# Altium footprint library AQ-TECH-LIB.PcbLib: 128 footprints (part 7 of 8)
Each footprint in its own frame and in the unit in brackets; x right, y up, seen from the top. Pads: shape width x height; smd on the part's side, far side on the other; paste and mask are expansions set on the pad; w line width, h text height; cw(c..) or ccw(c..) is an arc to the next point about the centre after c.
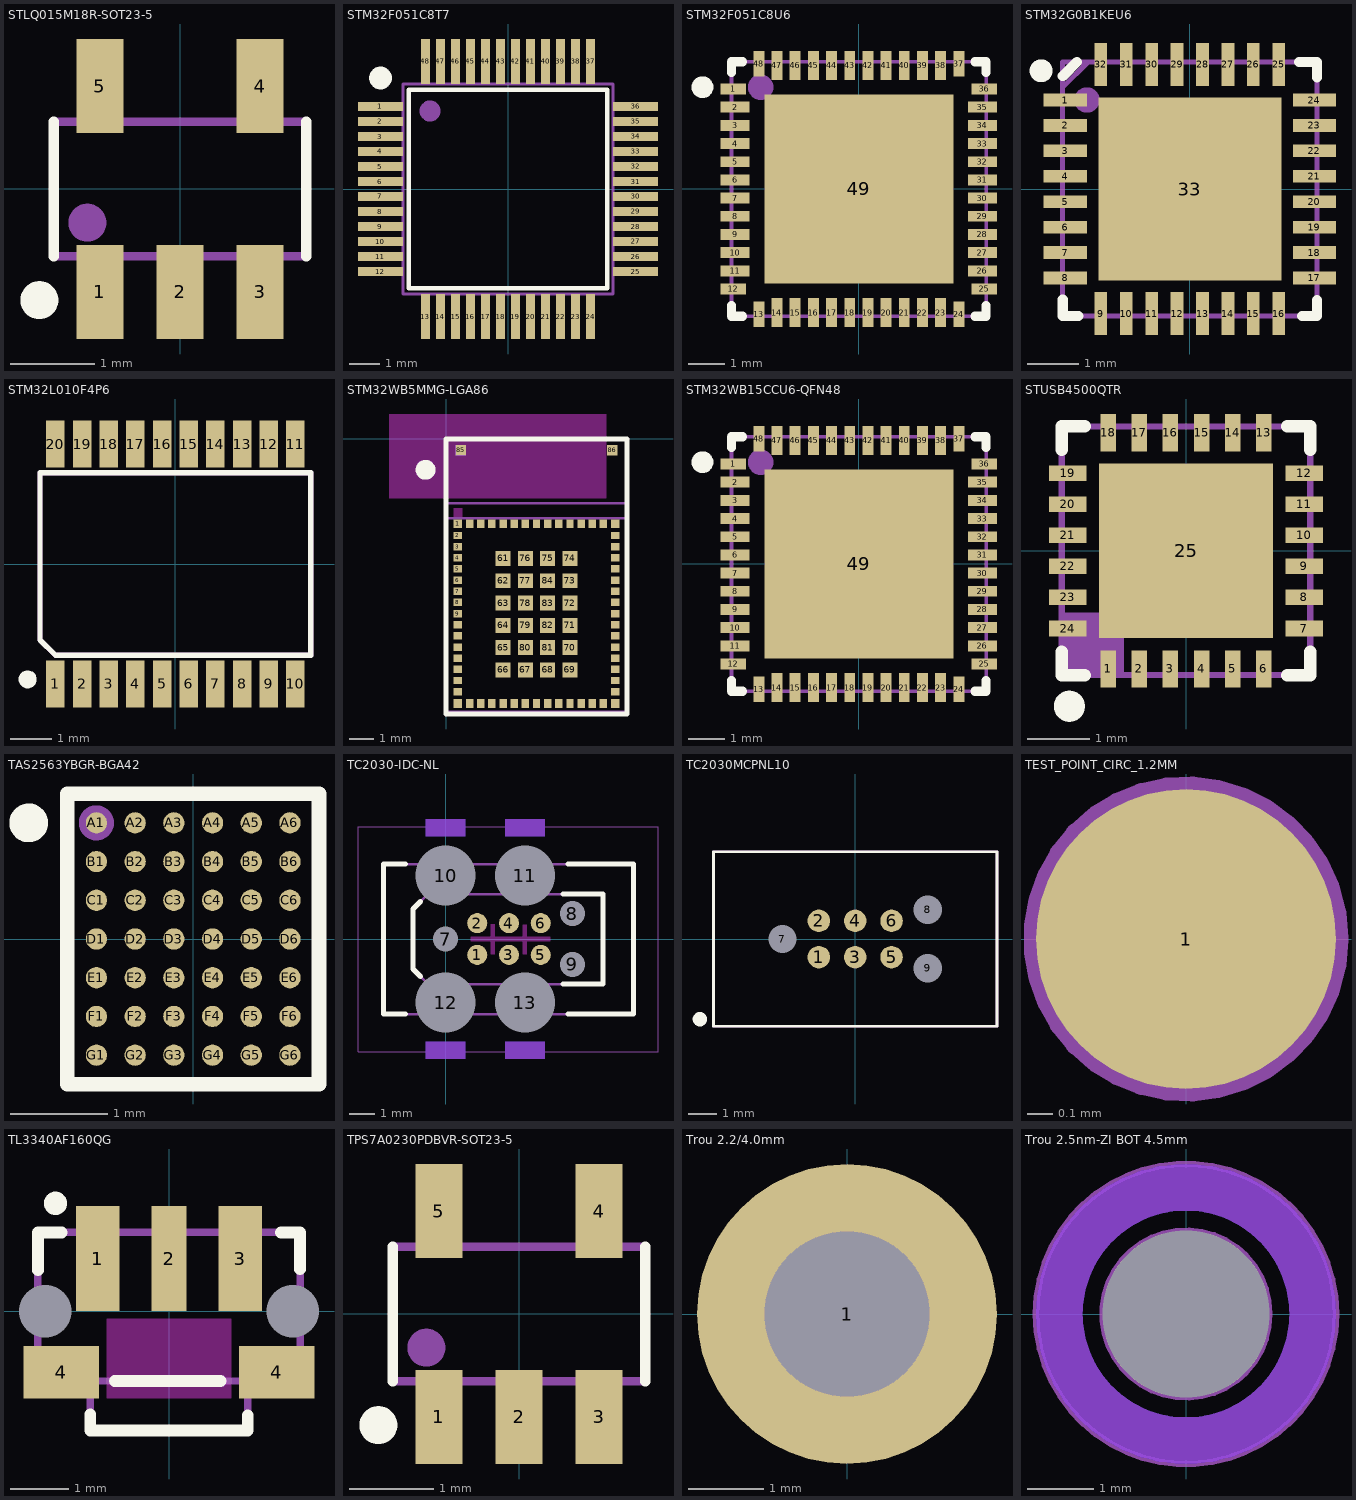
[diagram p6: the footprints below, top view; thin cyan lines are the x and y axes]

## STLQ015M18R-SOT23-5 [mil]
height 57.09
pads (5):
  rect 22x44 smd: 1(-37.4,-48.11) 2(0,-48.11) 3(37.4,-48.11) 4(37.4,48.11) 5(-37.4,48.11)
Top Overlay:
  lines w4.92: -59.06,-31.5 -59.06,31.5 ; 59.06,-31.5 59.06,31.5
  lines w9.84: -65.75,-55.91 ccw(c-65.75,-51.97) -65.75,-48.03 ccw(c-65.75,-51.97) -65.75,-55.91
Mechanical 3:
  lines w3.94: -59.06,-31.5 -59.06,31.5 59.06,31.5 59.06,-31.5 -59.06,-31.5
  lines w9.84: -43.31,-19.68 cw(c-43.31,-15.75) -43.31,-11.81 cw(c-43.31,-15.75) -43.31,-19.68
  text ".Designator" at -54.08,-9.65 h33.07
3D body "sot23-5.stp": height 43.31, standoff 0, extent -59.05,-49.2 59.06,49.22

## STM32F051C8T7 [mm]
height 1.6
pads (48):
  rect 1.5x0.3 smd paste+0 mask+0.05: 1(-4.25,2.75) 2(-4.25,2.25) 3(-4.25,1.75) 4(-4.25,1.25) 5(-4.25,0.75) 6(-4.25,0.25) 7(-4.25,-0.25) 8(-4.25,-0.75) 9(-4.25,-1.25) 10(-4.25,-1.75) 11(-4.25,-2.25) 12(-4.25,-2.75) 25(4.25,-2.75) 26(4.25,-2.25) 27(4.25,-1.75) 28(4.25,-1.25) 29(4.25,-0.75) 30(4.25,-0.25) 31(4.25,0.25) 32(4.25,0.75) 33(4.25,1.25) 34(4.25,1.75) 35(4.25,2.25) 36(4.25,2.75)
  rect 0.3x1.5 smd paste+0 mask+0.05: 13(-2.75,-4.25) 14(-2.25,-4.25) 15(-1.75,-4.25) 16(-1.25,-4.25) 17(-0.75,-4.25) 18(-0.25,-4.25) 19(0.25,-4.25) 20(0.75,-4.25) 21(1.25,-4.25) 22(1.75,-4.25) 23(2.25,-4.25) 24(2.75,-4.25) 37(2.75,4.25) 38(2.25,4.25) 39(1.75,4.25) 40(1.25,4.25) 41(0.75,4.25) 42(0.25,4.25) 43(-0.25,4.25) 44(-0.75,4.25) 45(-1.25,4.25) 46(-1.75,4.25) 47(-2.25,4.25) 48(-2.75,4.25)
Top Overlay:
  circle w0.4: c-4.25,3.7 r0.18
  lines w0.15: -3.3,-3.3 3.3,-3.3 3.3,3.3 -3.3,3.3 -3.3,-3.3
Mechanical 3:
  circle w0.4: c-2.6,2.6 r0.15
  lines w0.1: -3.5,-3.5 3.5,-3.5 3.5,3.5 -3.5,3.5 -3.5,-3.5
  text ".Designator" at -0.125,0.9 h0.84
3D body: height 1.6, standoff 0, extent -3.5,-3.5 3.5,3.5

## STM32F051C8U6 [mm] "UFQFPN48 7X7mm"
height 0.6
pads (49):
  rect 0.7x0.3 smd mask+0.05: 1(-3.45,2.75) 12(-3.45,-2.75) 25(3.45,-2.75) 36(3.45,2.75)
  rect 0.8x0.3 smd mask+0.05: 2(-3.4,2.25) 3(-3.4,1.75) 4(-3.4,1.25) 5(-3.4,0.75) 6(-3.4,0.25) 7(-3.4,-0.25) 8(-3.4,-0.75) 9(-3.4,-1.25) 10(-3.4,-1.75) 11(-3.4,-2.25) 26(3.4,-2.25) 27(3.4,-1.75) 28(3.4,-1.25) 29(3.4,-0.75) 30(3.4,-0.25) 31(3.4,0.25) 32(3.4,0.75) 33(3.4,1.25) 34(3.4,1.75) 35(3.4,2.25)
  rect 0.3x0.7 smd mask+0.05: 13(-2.75,-3.45) 24(2.75,-3.45) 37(2.75,3.45) 48(-2.75,3.45)
  rect 0.3x0.8 smd mask+0.05: 14(-2.25,-3.4) 15(-1.75,-3.4) 16(-1.25,-3.4) 17(-0.75,-3.4) 18(-0.25,-3.4) 19(0.25,-3.4) 20(0.75,-3.4) 21(1.25,-3.4) 22(1.75,-3.4) 23(2.25,-3.4) 38(2.25,3.4) 39(1.75,3.4) 40(1.25,3.4) 41(0.75,3.4) 42(0.25,3.4) 43(-0.25,3.4) 44(-0.75,3.4) 45(-1.25,3.4) 46(-1.75,3.4) 47(-2.25,3.4)
  rect 5.2x5.2 smd: 49(0,0)
Top Overlay:
  circle w0.3: c-4.3,2.8 r0.15
  lines w0.25: -3.5,-3.2 -3.5,-3.5 -3.2,-3.5 ; -3.5,3.2 -3.5,3.5 -3.2,3.5 ; 3.2,-3.5 3.5,-3.5 3.5,-3.2 ; 3.2,3.5 3.5,3.5 3.5,3.2
Mechanical 3:
  circle w0.4: c-2.7,2.8 r0.15
  lines w0.1: -3.5,-3.5 -3.5,3.5 3.5,3.5 3.5,-3.5 -3.5,-3.5
  text ".Designator" at -1.2,-0.1 h0.84
3D body: height 0.6, standoff 0, extent -3.5,-3.5 3.5,3.5
3D body: height 0.61, standoff 0, extent -2.898,2.201 -2.101,2.999

## STM32G0B1KEU6 [mm] "QFPN32-5X5mm"
height 0.6
pads (33):
  rect 0.85x0.25 smd mask+0.05: 1(-2.45,1.75) 2(-2.45,1.25) 3(-2.45,0.75) 4(-2.45,0.25) 5(-2.45,-0.25) 6(-2.45,-0.75) 7(-2.45,-1.25) 8(-2.45,-1.75) 17(2.45,-1.75) 18(2.45,-1.25) 19(2.45,-0.75) 20(2.45,-0.25) 21(2.45,0.25) 22(2.45,0.75) 23(2.45,1.25) 24(2.45,1.75)
  rect 0.25x0.85 smd mask+0.05: 9(-1.75,-2.45) 10(-1.25,-2.45) 11(-0.75,-2.45) 12(-0.25,-2.45) 13(0.25,-2.45) 14(0.75,-2.45) 15(1.25,-2.45) 16(1.75,-2.45) 25(1.75,2.45) 26(1.25,2.45) 27(0.75,2.45) 28(0.25,2.45) 29(-0.25,2.45) 30(-0.75,2.45) 31(-1.25,2.45) 32(-1.75,2.45)
  rect 3.6x3.6 smd mask+0.05: 33(0,0)
Top Overlay:
  circle w0.25: c-2.925,2.325 r0.1
  lines w0.2: -2.5,-2.17 -2.5,-2.5 -2.192,-2.5 ; -2.5,2.22 -2.218,2.5 ; 2.151,2.5 2.5,2.5 2.5,2.194 ; 2.208,-2.5 2.5,-2.5 2.5,-2.187
Mechanical 3:
  circle w0.3: c-2.025,1.75 r0.1
  lines w0.1: -2.5,2 -2,2.5 ; -2.5,-2.5 2.5,-2.5 2.5,2.5 -2.5,2.5 -2.5,-2.5
  text ".Designator" at -1.2,-0.1 h0.84
3D body "STM32G0B1KEU6.stp": height 0.6, standoff 0, extent -2.55,-2.55 2.55,2.55

## STM32L010F4P6 [mm] "refusion"
height 1.1
pads (20):
  rect 0.45x1.15 smd paste+0 mask+0.05: 1(-2.925,-2.925) 2(-2.275,-2.925) 3(-1.625,-2.925) 4(-0.975,-2.925) 5(-0.325,-2.925) 6(0.325,-2.925) 7(0.975,-2.925) 8(1.625,-2.925) 9(2.275,-2.925) 10(2.925,-2.925) 11(2.925,2.925) 12(2.275,2.925) 13(1.625,2.925) 14(0.975,2.925) 15(0.325,2.925) 16(-0.325,2.925) 17(-0.975,2.925) 18(-1.625,2.925) 19(-2.275,2.925) 20(-2.925,2.925)
Top Overlay:
  region: -3.6,-3.025 -3.642,-3.025 -3.72,-2.993 -3.78,-2.933 -3.812,-2.855 -3.812,-2.77 -3.78,-2.692 -3.72,-2.632 -3.642,-2.6 -3.6,-2.6 -3.558,-2.6 -3.48,-2.632 -3.42,-2.692 -3.387,-2.77 -3.388,-2.855 -3.42,-2.933 -3.48,-2.993 -3.558,-3.025
  lines w0.125: -3.3,-1.85 -3.3,2.225 3.3,2.225 3.3,-2.225 -2.925,-2.225 -3.3,-1.85
Mechanical 3:
  lines w0.125: -3.3,-1.85 -3.3,2.225 3.3,2.225 3.3,-2.225 -2.925,-2.225 -3.3,-1.85
  text "'.Designator'" at 0,0 h1
3D body "TSSOP20(refusion).stp": height 1.2, standoff 0, extent -3.3,-3.275 3.3,3.275

## STM32WB5MMG-LGA86 [mm] "7.3X11X1.4mm"
height 1.4
pads (86):
  rect 0.35x0.35 smd paste+0 mask+0.1: 1(0.475,-3.425) 17(0.475,-10.675) 31(6.825,-10.675) 47(6.825,-3.425)
  rect 0.35x0.3 smd paste+0 mask+0.1: 2(0.475,-3.9) 3(0.475,-4.35) 4(0.475,-4.8) 5(0.475,-5.25) 6(0.475,-5.7) 7(0.475,-6.15) 8(0.475,-6.6) 9(0.475,-7.05) 10(0.475,-7.5) 11(0.475,-7.95) 12(0.475,-8.4) 13(0.475,-8.85) 14(0.475,-9.3) 15(0.475,-9.75) 16(0.475,-10.2) 32(6.825,-10.2) 33(6.825,-9.75) 34(6.825,-9.3) 35(6.825,-8.85) 36(6.825,-8.4) 37(6.825,-7.95) 38(6.825,-7.5) 39(6.825,-7.05) 40(6.825,-6.6) 41(6.825,-6.15) 42(6.825,-5.7) 43(6.825,-5.25) 44(6.825,-4.8) 45(6.825,-4.35) 46(6.825,-3.9)
  rect 0.3x0.35 smd paste+0 mask+0.1: 18(0.95,-10.675) 19(1.4,-10.675) 20(1.85,-10.675) 21(2.3,-10.675) 22(2.75,-10.675) 23(3.2,-10.675) 24(3.65,-10.675) 25(4.1,-10.675) 26(4.55,-10.675) 27(5,-10.675) 28(5.45,-10.675) 29(5.9,-10.675) 30(6.35,-10.675) 48(6.35,-3.425) 49(5.9,-3.425) 50(5.45,-3.425) 51(5,-3.425) 52(4.55,-3.425) 53(4.1,-3.425) 54(3.65,-3.425) 55(3.2,-3.425) 56(2.75,-3.425) 57(2.3,-3.425) 58(1.85,-3.425) 59(1.4,-3.425) 60(0.95,-3.425)
  rect 0.6x0.6 smd paste+0 mask+0.1: 61(2.3,-4.825) 62(2.3,-5.725) 63(2.3,-6.625) 64(2.3,-7.525) 65(2.3,-8.425) 66(2.3,-9.325) 67(3.2,-9.325) 68(4.1,-9.325) 69(5,-9.325) 70(5,-8.425) 71(5,-7.525) 72(5,-6.625) 73(5,-5.725) 74(5,-4.825) 75(4.1,-4.825) 76(3.2,-4.825) 77(3.2,-5.725) 78(3.2,-6.625) 79(3.2,-7.525) 80(3.2,-8.425) 81(4.1,-8.425) 82(4.1,-7.525) 83(4.1,-6.625) 84(4.1,-5.725)
  rect 0.43x0.43 smd paste+0 mask+0.1: 85(0.6,-0.465) 86(6.7,-0.465)
Top Layer keep-out:
  rectangle: 0.295,-3.145 0.655,-2.8
Top Overlay:
  circle w0.5: c-0.825,-1.25 r0.15
  lines w0.2: 0,-11.1 7.3,-11.1 7.3,0 0,0 0,-11.1
Keep-Out Layer:
  rectangle: -2.3,-2.4 6.475,1
Mechanical 3:
  lines w0.1: 0,-3.2 7.3,-3.2 ; 0,-2.6 7.3,-2.6 ; 0,-11 0,0 7.3,0 7.3,-11 0,-11
  text ".Designator" at 3.6,-6.875 h0.84
3D body: height 1.41, standoff 0, extent 0.351,-1.35 0.849,-0.851
3D body: height 1.4, standoff 0, extent 0,-11 7.3,0

## STM32WB15CCU6-QFN48 [mm] "UFQFPN48 7X7mm"
height 0.6
pads (49):
  rect 0.7x0.3 smd mask+0.05: 1(-3.45,2.75) 12(-3.45,-2.75) 25(3.45,-2.75) 36(3.45,2.75)
  rect 0.8x0.3 smd mask+0.05: 2(-3.4,2.25) 3(-3.4,1.75) 4(-3.4,1.25) 5(-3.4,0.75) 6(-3.4,0.25) 7(-3.4,-0.25) 8(-3.4,-0.75) 9(-3.4,-1.25) 10(-3.4,-1.75) 11(-3.4,-2.25) 26(3.4,-2.25) 27(3.4,-1.75) 28(3.4,-1.25) 29(3.4,-0.75) 30(3.4,-0.25) 31(3.4,0.25) 32(3.4,0.75) 33(3.4,1.25) 34(3.4,1.75) 35(3.4,2.25)
  rect 0.3x0.7 smd mask+0.05: 13(-2.75,-3.45) 24(2.75,-3.45) 37(2.75,3.45) 48(-2.75,3.45)
  rect 0.3x0.8 smd mask+0.05: 14(-2.25,-3.4) 15(-1.75,-3.4) 16(-1.25,-3.4) 17(-0.75,-3.4) 18(-0.25,-3.4) 19(0.25,-3.4) 20(0.75,-3.4) 21(1.25,-3.4) 22(1.75,-3.4) 23(2.25,-3.4) 38(2.25,3.4) 39(1.75,3.4) 40(1.25,3.4) 41(0.75,3.4) 42(0.25,3.4) 43(-0.25,3.4) 44(-0.75,3.4) 45(-1.25,3.4) 46(-1.75,3.4) 47(-2.25,3.4)
  rect 5.2x5.2 smd: 49(0,0)
Top Overlay:
  circle w0.3: c-4.3,2.8 r0.15
  lines w0.25: -3.5,-3.2 -3.5,-3.5 -3.2,-3.5 ; -3.5,3.2 -3.5,3.5 -3.2,3.5 ; 3.2,-3.5 3.5,-3.5 3.5,-3.2 ; 3.2,3.5 3.5,3.5 3.5,3.2
Mechanical 3:
  circle w0.4: c-2.7,2.8 r0.15
  lines w0.1: -3.5,-3.5 3.5,-3.5 3.5,3.5 -3.5,3.5 -3.5,-3.5
  text ".Designator" at -1.2,-0.1 h0.84
3D body: height 0.61, standoff 0, extent -2.898,2.201 -2.101,2.999
3D body: height 0.6, standoff 0, extent -3.5,-3.5 3.5,3.5

## STUSB4500QTR [mm] "QFN24 4X4mm"
height 1
pads (25):
  rect 0.25x0.6 smd paste+0 mask+0.05: 1(-1.25,-1.9) 2(-0.75,-1.9) 3(-0.25,-1.9) 4(0.25,-1.9) 5(0.75,-1.9) 6(1.25,-1.9) 13(1.25,1.9) 14(0.75,1.9) 15(0.25,1.9) 16(-0.25,1.9) 17(-0.75,1.9) 18(-1.25,1.9)
  rect 0.6x0.25 smd paste+0 mask+0.05: 7(1.9,-1.25) 8(1.9,-0.75) 9(1.9,-0.25) 10(1.9,0.25) 11(1.9,0.75) 12(1.9,1.25) 19(-1.9,1.25) 20(-1.9,0.75) 21(-1.9,0.25) 22(-1.9,-0.25) 23(-1.9,-0.75) 24(-1.9,-1.25)
  rect 2.8x2.8 smd paste+0 mask+0.05: 25(0,0)
Top Overlay:
  lines w0.2: -2,-1.625 -2,-2 -1.625,-2 ; -2,1.625 -2,2 -1.625,2 ; 1.625,-2 2,-2 2,-1.625 ; 1.625,2 2,2 2,1.625
  lines w0.25: -1.875,-2.625 ccw(c-1.875,-2.5) -1.875,-2.375 ccw(c-1.875,-2.5) -1.875,-2.625
Mechanical 3:
  region: -2,-2 -1,-2 -1,-1 -2,-1
  lines w0.1: -2,-2 2,-2 2,2 -2,2 -2,-2
  text ".Designator" at 0,0 h0.84
3D body: height 1.01, standoff 0, extent -2,-2 -1,-1
3D body: height 1, standoff 0, extent -2,-2 2,2

## TAS2563YBGR-BGA42 [mm] "pas 0.4mm"
height 0.5
pads (42):
  round 0.22 smd mask+0.04: A1(-1,1.2) A2(-0.6,1.2) A3(-0.2,1.2) A4(0.2,1.2) A5(0.6,1.2) A6(1,1.2) B1(-1,0.8) B2(-0.6,0.8) B3(-0.2,0.8) B4(0.2,0.8) B5(0.6,0.8) B6(1,0.8) C1(-1,0.4) C2(-0.6,0.4) C3(-0.2,0.4) C4(0.2,0.4) C5(0.6,0.4) C6(1,0.4) D1(-1,0) D2(-0.6,0) D3(-0.2,0) D4(0.2,0) D5(0.6,0) D6(1,0) E1(-1,-0.4) E2(-0.6,-0.4) E3(-0.2,-0.4) E4(0.2,-0.4) E5(0.6,-0.4) E6(1,-0.4) F1(-1,-0.8) F2(-0.6,-0.8) F3(-0.2,-0.8) F4(0.2,-0.8) F5(0.6,-0.8) F6(1,-0.8) G1(-1,-1.2) G2(-0.6,-1.2) G3(-0.2,-1.2) G4(0.2,-1.2) G5(0.6,-1.2) G6(1,-1.2)
Top Overlay:
  circle w0.2: c-1.7,1.2 r0.1
  lines w0.15: -1.3,-1.5 -1.3,1.5 1.3,1.5 1.3,-1.5 -1.3,-1.5
Mechanical 3:
  circle w0.2: c-1,1.2 r0.081
  lines w0.1: -1.3,-1.5 -1.3,1.5 1.3,1.5 1.3,-1.5 -1.3,-1.5
  text "1" at -1.1,1.7 h0.5
  text "G" at -1.8,-1.4 h0.5
  text "6" at 0.9,1.7 h0.5
  text "A" at -1.8,1.1 h0.5
  text ".Designator" at -0.6,-0.4 h0.84
3D body: height 0.5, standoff 0, extent -1.3,-1.5 1.3,1.5
3D body: height 0.51, standoff 0, extent -1.124,1.075 -0.875,1.325

## TC2030-IDC-NL [mm]
height 27
pads (13):
  round 0.8 smd paste-0.8 mask+0.1: 1(1.27,-0.635) 2(1.27,0.635) 3(2.54,-0.635) 4(2.54,0.635) 5(3.81,-0.635) 6(3.81,0.635)
  round 0.97 / inner round 0 / far side round 0.97 hole 1 unplated paste+0 mask+0.1: 7(0,0) 8(5.08,1.016) 9(5.08,-1.016)
  round 2.37 / inner round 0 / far side round 2.37 hole 2.4 unplated paste+0 mask+0.1: 10(0,2.54) 11(3.175,2.54) 12(0,-2.54) 13(3.175,-2.54)
Top Layer keep-out:
  rectangle: 3.075,-0.625 3.25,0.575
  rectangle: 1.8,-0.625 1.975,0.6
  rectangle: 1,-0.1 4.2,0.1
Bottom Layer keep-out:
  rectangle: -0.8,-4.8 0.8,-4.1
  rectangle: 2.375,-4.8 3.975,-4.1
  region: 3.975,4.8 2.375,4.8 2.375,4.1 3.975,4.1
  region: 0.8,4.8 -0.8,4.8 -0.8,4.1 0.8,4.1
Top Overlay:
  lines w0.2: -1.6,-3 -2.475,-3 -2.475,3 -1.6,3 ; -1,-1.5 -1.3,-1.2 -1.3,1.2 -1,1.5 ; 4.7,-1.8 6.3,-1.8 6.3,1.8 4.7,1.8 ; 4.9,-3 7.525,-3 7.525,3 4.9,3
Mechanical 1:
  lines w0.05: -3.5,-4.5 -3.5,4.5 8.5,4.5 8.5,-4.5 -3.5,-4.5
Mechanical 3:
  lines w0.1: -2.475,-3 7.525,-3 7.525,3 -2.475,3 -2.475,-3 ; -1.3,-1.2 -1.3,1.2 -0.7,1.8 6.3,1.8 6.3,-1.8 -0.7,-1.8 -1.3,-1.2
  text "6" at 4.006,1.584 h0.42
  text "1" at 1.355,-1.2 h0.42
  text ".Designator" at 3.325,0.425 h0.84
  text "2" at 1.355,1.584 h0.42
3D body: height 27, standoff 8, extent -2.475,-3 7.525,3
3D body: height 8, standoff 0, extent -1.3,-1.8 6.3,1.8

## TC2030MCPNL10 [mm]
pads (9):
  round 0.787 smd: 1(-1.27,-0.635) 2(-1.27,0.635) 3(0,-0.635) 4(0,0.635) 5(1.27,-0.635) 6(1.27,0.635)
  round 0.495 hole 0.991 unplated: 7(-2.54,0) 8(2.54,1.016) 9(2.54,-1.016)
Top Overlay:
  circle w0.3: c-5.425,-2.8 r0.1
  lines w0.1: -4.953,-3.048 -4.953,3.048 4.953,3.048 4.953,-3.048 -4.953,-3.048
Mechanical 3:
  lines w0.1: -4.953,-3.048 4.953,-3.048 4.953,3.048 -4.953,3.048 -4.953,-3.048
  text ".Designator" at -0.075,-0.051 h0.84
3D body "TC2030-MCP-NL-10.stp": height 25.67, standoff -5.7, extent -4.953,-3.048 4.953,3.048

## TEST_POINT_CIRC_1.2MM [mm]
pads (1):
  round 1.2 smd paste-1.5 mask+0.05: 1(0,0)
Mechanical 3:
  circle w0.1: c0,0 r0.6
  text "'.Designator'" at 0.247,-0.547 h0.8

## TL3340AF160QG [mm]
height 3.3
pads (7):
  rect 0.75x1.8 smd: 1(-1.225,0.9) 3(1.225,0.9)
  rect 0.6x1.8 smd: 2(0,0.9)
  rect 1.3x0.9 smd: 4(-1.85,-1.05) 4(1.85,-1.05)
  round 0 hole 0.9 unplated mask+0.1: 5(-2.125,0) 5(2.125,0)
Top Layer keep-out:
  rectangle: -1.075,-1.5 1.075,-0.125
Top Overlay:
  circle w0.2: c-1.95,1.85 r0.1
  lines w0.2: -2.25,0.698 -2.25,1.35 -1.842,1.35 ; -1.35,-1.771 -1.35,-2.05 1.35,-2.05 1.35,-1.787 ; -0.934,-1.2 0.883,-1.2 ; 1.922,1.35 2.25,1.35 ; 2.086,1.35 2.25,1.35 ; 2.25,0.72 2.25,1.35
Mechanical 3:
  lines w0.127: -1.35,-0.895 -1.35,-2.05 1.35,-2.05 1.35,-0.895 ; -2.25,-1.2 2.25,-1.2 2.25,1.35 -2.25,1.35 -2.25,-1.2
  text ".Designator" at 0.354,-0.541 h0.84
3D body "TL3340AF160QG.stp": height 3.26, standoff -0.49, extent -2.25,-2.05 2.25,1.615

## TPS7A0230PDBVR-SOT23-5 [mil] "refusion"
height 57.09
pads (5):
  rect 22x44 smd paste+0 mask+3.94: 1(-37.4,-48.11) 2(0,-48.11) 3(37.4,-48.11) 4(37.4,48.11) 5(-37.4,48.11)
Top Overlay:
  lines w4.92: -59.06,-31.5 -59.06,31.5 ; 59.06,-31.5 59.06,31.5
  lines w9.84: -65.75,-55.91 ccw(c-65.75,-51.97) -65.75,-48.03 ccw(c-65.75,-51.97) -65.75,-55.91
Mechanical 3:
  lines w3.94: -59.06,-31.5 -59.06,31.5 59.06,31.5 59.06,-31.5 -59.06,-31.5
  lines w9.84: -43.31,-19.68 cw(c-43.31,-15.75) -43.31,-11.81 cw(c-43.31,-15.75) -43.31,-19.68
  text ".Designator" at -54.08,-9.65 h33.07
3D body "sot23-5.stp": height 43.31, standoff 0, extent -59.05,-49.2 59.06,49.22

## Trou 2.2/4.0mm [mm]
pads (1):
  round 4 hole 2.2 paste+0: 1(0,0)
Mechanical 3:
  circle w0.1: c0,0 r1.1
  text "'.Designator'" at -0.247,0.547 h0.8

## Trou 2.5nm-ZI BOT 4.5mm [mm]
pads (1):
  round 0 hole 2.5 paste+0 mask+1.35: 1(0,0)
Bottom Layer keep-out:
  circle w0.7: c0,0 r1.9
Mechanical 3:
  circle w0.1: c0,0 r1.25
Mechanical 13:
  circle w0.1: c0,0 r2.25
